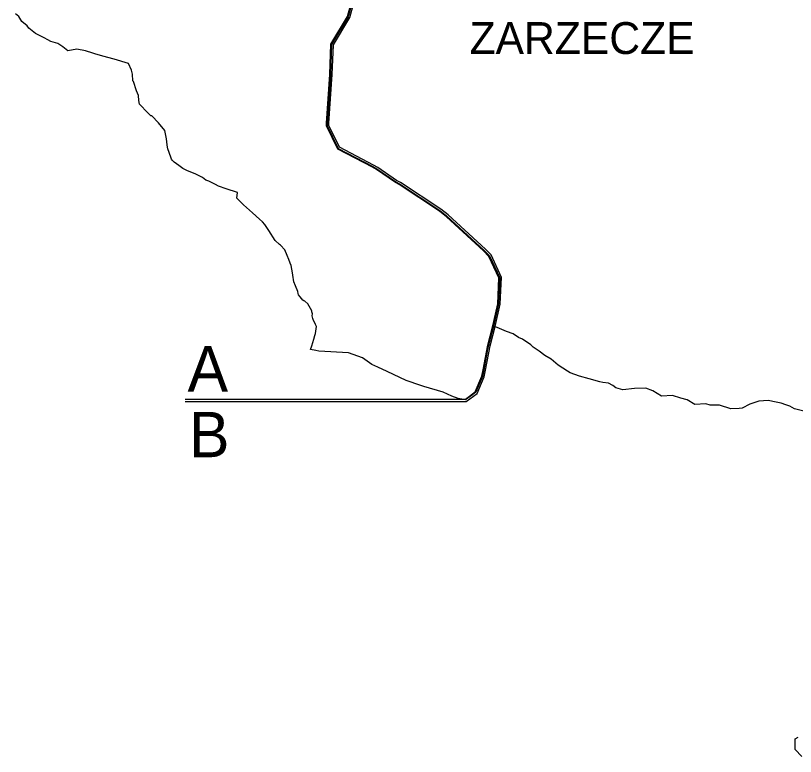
# Model space of a CAD drawing. Extents: x -562952 to -547638, y 190691 to 208158.
# Drawn here: x -561097 to -556696, y 194199 to 198378 of the extents above; entities that cross this region are included whole.
import ezdxf

# ---------------------------------------------------------------- set-up
doc = ezdxf.new("R2010")
doc.units = 0
for name, color, linetype in [('granica A_B', 7, 'Continuous'), ('granica_gminy', 7, 'Continuous'), ('granica_sołectwa', 7, 'Continuous'), ('nazwy miejscowości DUŻE', 7, 'Continuous'), ('obwódka', 7, 'Continuous')]:
    doc.layers.add(name, color=color, linetype=linetype)

msp = doc.modelspace()

# ---------------------------------------------------------------- linework, layer by layer
at = {"layer": 'granica A_B'}
for points in [[(-560139.5, 196214.9), (-558558, 196214.9), (-558503, 196255.2), (-558465.2, 196343.4), (-558458.7, 196379.7), (-558432.2, 196518.7), (-558403.7, 196627.3), (-558375.9, 196752.6), (-558368.5, 196897.9), (-558425.3, 197019.6), (-558455.2, 197050.6), (-558664.9, 197242.5), (-558704.5, 197275), (-558932.2, 197424.8), (-558953.4, 197435.6), (-559059.7, 197509.6), (-559083.2, 197522.2), (-559278.7, 197625.1), (-559342.6, 197755.4), (-559341.9, 197771.6), (-559323.4, 198045.4), (-559316.9, 198216.1), (-559223.6, 198372.7), (-559184, 198517.3)], [(-560139.5, 196200.9), (-558553.4, 196200.9), (-558491.6, 196246.2), (-558451.7, 196339.4), (-558444.9, 196377.2), (-558418.6, 196515.7), (-558390.1, 196624), (-558362, 196750.7), (-558354.4, 196900.6), (-558413.6, 197027.7), (-558445.5, 197060.6), (-558655.7, 197253.1), (-558696.2, 197286.3), (-558925.1, 197436.9), (-558946.2, 197447.7), (-559052.4, 197521.6), (-559076.6, 197534.6), (-559268.1, 197635.4), (-559328.5, 197758.3), (-559327.9, 197770.8), (-559309.4, 198044.7), (-559303.1, 198212), (-559210.6, 198367.2), (-559170.4, 198514)]]:
    msp.add_lwpolyline(points, dxfattribs=at)
at = {"layer": 'granica_gminy'}
for points in [[(-556649, 196146.8), (-556701.3, 196160.3), (-556727.8, 196175.3), (-556750, 196182.2), (-556776.7, 196190.9), (-556803.9, 196198), (-556849.1, 196207), (-556902.6, 196202.4), (-556952.6, 196186), (-556996.3, 196162.9), (-557012.4, 196162.1), (-557060.3, 196158.6), (-557123.3, 196181.1), (-557177, 196180.8), (-557200.6, 196188.3), (-557262.5, 196183.1), (-557306.7, 196209.7), (-557342, 196220.4), (-557389.4, 196233.9), (-557451.9, 196231), (-557500.1, 196260.3), (-557540.4, 196276.4), (-557604.1, 196274.4), (-557669.7, 196266.6), (-557708.8, 196278.7), (-557726.3, 196290.2), (-557749.6, 196303.4), (-557782.4, 196307.5), (-557798.8, 196312.6), (-557860, 196329), (-557914, 196344.5), (-557967.2, 196362.9), (-557982.4, 196372.4), (-558034.7, 196405.7), (-558074.4, 196440), (-558108.9, 196460.6), (-558141.7, 196484.8), (-558175, 196507.8), (-558189.7, 196521.1), (-558235.4, 196553.3), (-558258.7, 196562.8), (-558287.7, 196581.8), (-558326, 196596.4), (-558378.1, 196617.8), (-558399.8, 196626.3), (-558428.3, 196517.9), (-558432.9, 196494.4), (-558454.7, 196379), (-558461.3, 196342.2), (-558499.7, 196252.6), (-558517.5, 196239.4), (-558556.7, 196210.9), (-558599.6, 196217.5), (-558635.1, 196230.3), (-558684.4, 196252.6), (-558792.8, 196284.6), (-558810.4, 196290.3), (-558891.5, 196319.2), (-558999.9, 196370.5), (-559052.5, 196394.6), (-559086.5, 196409.4), (-559138.2, 196447.3), (-559218.7, 196474.7), (-559386.1, 196484.3), (-559402.8, 196488.8), (-559431.4, 196495), (-559424.4, 196515.7), (-559413.6, 196552.5), (-559407.6, 196572.8), (-559403.7, 196584.5), (-559397.5, 196623), (-559403.4, 196636), (-559417.1, 196663.5), (-559419.2, 196669.4), (-559423.1, 196683.2), (-559421.5, 196695.4), (-559422.4, 196700.4), (-559424.6, 196707.1), (-559424, 196710.7), (-559425.3, 196713), (-559447.1, 196752.4), (-559464.2, 196766.5), (-559470.1, 196767.9), (-559474.8, 196773.3), (-559490.1, 196790.9), (-559500.3, 196803), (-559501.2, 196810.9), (-559504.7, 196822), (-559516.4, 196852.9), (-559525.9, 196875.8), (-559532, 196913.8), (-559534.6, 196927.1), (-559541.7, 196967.9), (-559547.2, 196981.6), (-559554.6, 197001.2), (-559563.5, 197024), (-559578, 197056.7), (-559602.4, 197082.7), (-559606.9, 197086.9), (-559630.9, 197108.7), (-559668, 197164.8), (-559690.6, 197198.4), (-559703.8, 197214.5), (-559719.2, 197229.5), (-559758.9, 197265.7), (-559809.5, 197309.7), (-559847.5, 197347.2), (-559843.9, 197380.3), (-559907.3, 197400.5), (-559952, 197415.6), (-559968, 197424.1), (-560006.6, 197443.7), (-560023, 197449.8), (-560041.9, 197463.5), (-560079, 197483.1), (-560129.9, 197504.4), (-560152.3, 197515.7), (-560175.3, 197531.5), (-560202.6, 197550.3), (-560211.9, 197560.9), (-560215.9, 197566.9), (-560220.6, 197579.3), (-560237.9, 197625.5), (-560239, 197635.7), (-560240.5, 197648.1), (-560245.4, 197683), (-560253.5, 197728.9), (-560289.8, 197772.8), (-560328.1, 197813), (-560333.6, 197813.1), (-560349.4, 197828.9), (-560397.3, 197877.4), (-560401.9, 197897.9), (-560402.9, 197926.1), (-560413.7, 197953.6), (-560430.9, 198006), (-560435.4, 198009.9), (-560437.7, 198048.1), (-560442.5, 198069.9), (-560459.2, 198107), (-560540.5, 198131.5), (-560604.7, 198148.7), (-560648.9, 198162.4), (-560660.5, 198166.3), (-560702.3, 198179.5), (-560750.2, 198187.5), (-560801.8, 198178.5), (-560830.8, 198201.2), (-560857.5, 198220.2), (-560897.3, 198232.3), (-560914.3, 198241.4), (-560934.6, 198252.1), (-560984.2, 198277.4), (-561021, 198307.4), (-561030.7, 198320.7), (-561062.1, 198343.8), (-561077.5, 198371.9), (-561096.6, 198387.6)], [(-556659.2, 194199.1), (-556696.8, 194238.3), (-556697.4, 194298.2), (-556681, 194307.6)]]:
    msp.add_lwpolyline(points, dxfattribs=at)
at = {"layer": 'granica_sołectwa'}
msp.add_lwpolyline([(-559180.1, 198516.4), (-559219.9, 198371.1), (-559313, 198215), (-559319.4, 198045.2), (-559337.9, 197771.4), (-559338.6, 197756.2), (-559275.7, 197628), (-559081.3, 197525.7), (-559057.6, 197513), (-558951.4, 197439.1), (-558930.2, 197428.2), (-558702.1, 197278.3), (-558662.3, 197245.6), (-558452.4, 197053.5), (-558421.9, 197021.9), (-558364.5, 196898.6), (-558371.9, 196752), (-558399.8, 196626.3)], dxfattribs=at)
at = {"layer": 'obwódka'}
for points in [[(-556649, 196146.8), (-556701.3, 196160.3), (-556727.8, 196175.3), (-556750, 196182.2), (-556776.7, 196190.9), (-556803.9, 196198), (-556849.1, 196207), (-556902.6, 196202.4), (-556952.6, 196186), (-556996.3, 196162.9), (-557012.4, 196162.1), (-557060.3, 196158.6), (-557123.3, 196181.1), (-557177, 196180.8), (-557200.6, 196188.3), (-557262.5, 196183.1), (-557306.7, 196209.7), (-557342, 196220.4), (-557389.4, 196233.9), (-557451.9, 196231), (-557500.1, 196260.3), (-557540.4, 196276.4), (-557604.1, 196274.4), (-557669.7, 196266.6), (-557708.8, 196278.7), (-557726.3, 196290.2), (-557749.6, 196303.4), (-557782.4, 196307.5), (-557798.8, 196312.6), (-557860, 196329), (-557914, 196344.5), (-557967.2, 196362.9), (-557982.4, 196372.4), (-558034.7, 196405.7), (-558074.4, 196440), (-558108.9, 196460.6), (-558141.7, 196484.8), (-558175, 196507.8), (-558189.7, 196521.1), (-558235.4, 196553.3), (-558258.7, 196562.8), (-558287.7, 196581.8), (-558326, 196596.4), (-558378.1, 196617.8), (-558399.8, 196626.3), (-558428.3, 196517.9), (-558432.9, 196494.4), (-558454.7, 196379), (-558461.3, 196342.2), (-558499.7, 196252.6), (-558517.5, 196239.4), (-558556.7, 196210.9), (-558599.6, 196217.5), (-558635.1, 196230.3), (-558684.4, 196252.6), (-558792.8, 196284.6), (-558810.4, 196290.3), (-558891.5, 196319.2), (-558999.9, 196370.5), (-559052.5, 196394.6), (-559086.5, 196409.4), (-559138.2, 196447.3), (-559218.7, 196474.7), (-559386.1, 196484.3), (-559402.8, 196488.8), (-559431.4, 196495), (-559424.4, 196515.7), (-559413.6, 196552.5), (-559407.6, 196572.8), (-559403.7, 196584.5), (-559397.5, 196623), (-559403.4, 196636), (-559417.1, 196663.5), (-559419.2, 196669.4), (-559423.1, 196683.2), (-559421.5, 196695.4), (-559422.4, 196700.4), (-559424.6, 196707.1), (-559424, 196710.7), (-559425.3, 196713), (-559447.1, 196752.4), (-559464.2, 196766.5), (-559470.1, 196767.9), (-559474.8, 196773.3), (-559490.1, 196790.9), (-559500.3, 196803), (-559501.2, 196810.9), (-559504.7, 196822), (-559516.4, 196852.9), (-559525.9, 196875.8), (-559532, 196913.8), (-559534.6, 196927.1), (-559541.7, 196967.9), (-559547.2, 196981.6), (-559554.6, 197001.2), (-559563.5, 197024), (-559578, 197056.7), (-559602.4, 197082.7), (-559606.9, 197086.9), (-559630.9, 197108.7), (-559668, 197164.8), (-559690.6, 197198.4), (-559703.8, 197214.5), (-559719.2, 197229.5), (-559758.9, 197265.7), (-559809.5, 197309.7), (-559847.5, 197347.2), (-559843.9, 197380.3), (-559907.3, 197400.5), (-559952, 197415.6), (-559968, 197424.1), (-560006.6, 197443.7), (-560023, 197449.8), (-560041.9, 197463.5), (-560079, 197483.1), (-560129.9, 197504.4), (-560152.3, 197515.7), (-560175.3, 197531.5), (-560202.6, 197550.3), (-560211.9, 197560.9), (-560215.9, 197566.9), (-560220.6, 197579.3), (-560237.9, 197625.5), (-560239, 197635.7), (-560240.5, 197648.1), (-560245.4, 197683), (-560253.5, 197728.9), (-560289.8, 197772.8), (-560328.1, 197813), (-560333.6, 197813.1), (-560349.4, 197828.9), (-560397.3, 197877.4), (-560401.9, 197897.9), (-560402.9, 197926.1), (-560413.7, 197953.6), (-560430.9, 198006), (-560435.4, 198009.9), (-560437.7, 198048.1), (-560442.5, 198069.9), (-560459.2, 198107), (-560540.5, 198131.5), (-560604.7, 198148.7), (-560648.9, 198162.4), (-560660.5, 198166.3), (-560702.3, 198179.5), (-560750.2, 198187.5), (-560801.8, 198178.5), (-560830.8, 198201.2), (-560857.5, 198220.2), (-560897.3, 198232.3), (-560914.3, 198241.4), (-560934.6, 198252.1), (-560984.2, 198277.4), (-561021, 198307.4), (-561030.7, 198320.7), (-561062.1, 198343.8), (-561077.5, 198371.9), (-561096.6, 198387.6)], [(-556659.2, 194199.1), (-556696.8, 194238.3), (-556697.4, 194298.2), (-556681, 194307.6)]]:
    msp.add_lwpolyline(points, dxfattribs=at)

# ---------------------------------------------------------------- texts
at = {"layer": 'granica A_B'}
for s, p in [('A', (-560125.9, 196257.1)), ('B', (-560117.7, 195886.5))]:
    msp.add_text(s, height=256, rotation=360, dxfattribs=at).set_placement(p)
at = {"layer": 'nazwy miejscowości DUŻE'}
msp.add_text('ZARZECZE', height=180, dxfattribs=at).set_placement((-558535, 198160.8))

doc.saveas('drawing.dxf')
